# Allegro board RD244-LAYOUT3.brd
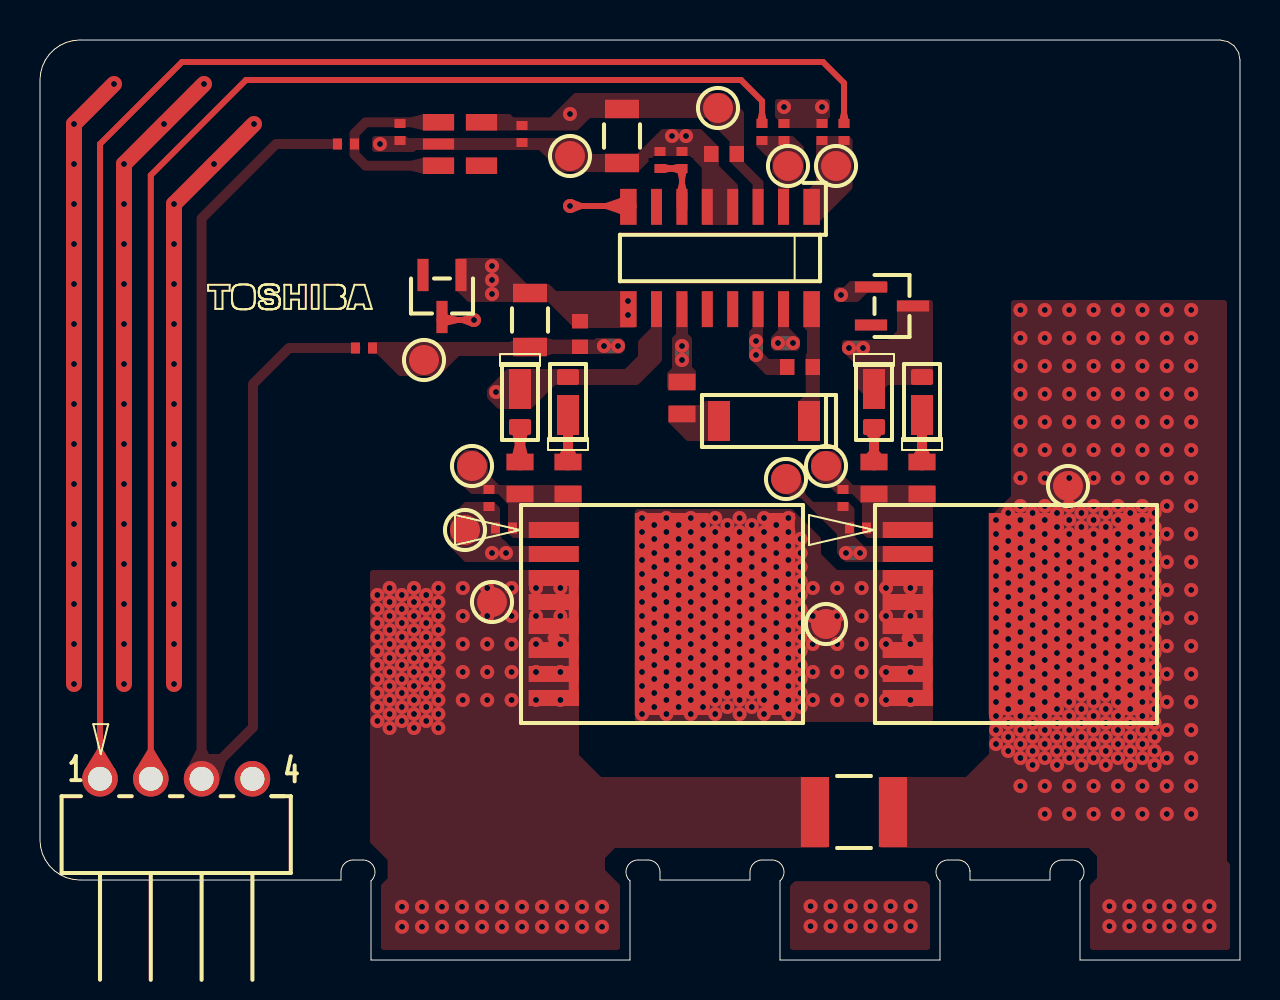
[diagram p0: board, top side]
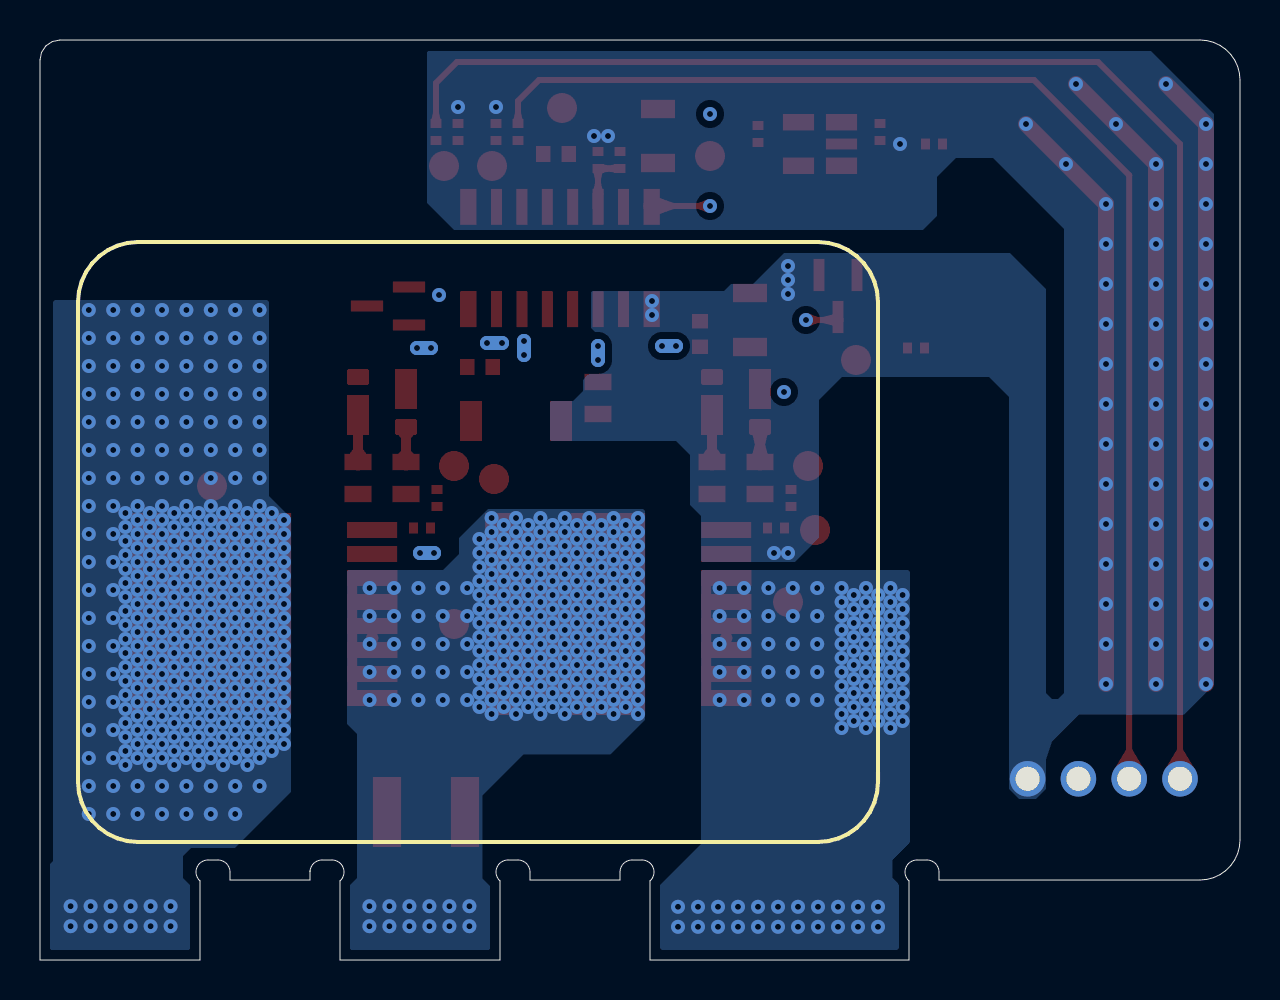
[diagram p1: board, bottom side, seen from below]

Outline 60 x 46 mm; copper layers: TOP, CONDUCTIVE2, CONDUCTIVE3, CONDUCTIVE4, CONDUCTIVE5, BOTTOM. Coordinates in mm from the lower left corner of the outline.
Outline path: 0,44 0.03,44.35 0.12,44.68 0.27,45 0.47,45.29 0.71,45.53 1,45.73 1.32,45.88 1.65,45.97 2,46 59,46 59.39,45.92 59.71,45.71 59.93,45.37 60,45 60,0 52,0 52,3.95 arc(52.16,4.61) 51.6,5 51.1,5 arc(50.68,4.82) 50.5,4.4 50.5,4 46.5,4 46.5,4.45 46.5,4.45 arc(46.31,4.84) 45.9,5 45.4,5 arc(44.84,4.61) 45,3.95 45,0 37,0 37,3.95 arc(37.16,4.61) 36.6,5 36.1,5 arc(35.68,4.82) 35.5,4.4 35.5,4 31,4 31,4.4 arc(30.82,4.82) 30.4,5 29.9,5 arc(29.34,4.61) 29.5,3.95 29.5,0 16.55,0 16.55,3.95 arc(16.71,4.61) 16.15,5 15.65,5 arc(15.23,4.82) 15.05,4.4 15.05,4 2,4 1.65,4.03 1.32,4.12 1,4.27 0.71,4.47 0.47,4.71 0.27,5 0.12,5.32 0.03,5.65 0,6 0,44

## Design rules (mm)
constraint set DEFAULT: 

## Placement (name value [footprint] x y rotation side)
C701  -  [FTP_65]  39.1 41.4 270 top
C702  -  [FTP_65]  37.2 41.4 270 top
C703  -  [FTP_65]  32.1 40 270 top
C704  -  [FTP_15]  29.1 41.2 90 top
C705  -  [KC01670AKP]  34.2 40.3 0 top
C706  -  [KC01670AKP]  38 29.65 0 top
C707  -  [FTP_15]  24.5 32 270 top
C708  -  [KC01670AKP]  27 31.3 270 top
C709  -  [FTP_65]  40.9 21.6 0 top
C710  -  [FTP_65]  23.2 21.6 0 top
C711  -  [DC835R1AKP]  40.7 7.4 0 top
C712  -  [FTP_65]  18 41.4 90 top
C713  -  [FTP_65]  24.1 41.3 90 top
CN702  -  [LOCAL_TSW_104_08_G_S_RA_A]  3 9.06 0 top
D701  -  [FTP_81]  36.2 26.95 0 top
D702  -  [US2H_A]  44.1 27.9 90 top
D703  -  [FTP_27]  42.6 32.7 270 top
D704  -  [US2H_A]  41.7 27.9 270 top
D705  -  [US2H_A]  26.4 27.9 90 top
D706  -  [FTP_27]  20.1 33.2 180 top
D707  -  [US2H_A]  24 27.9 270 top
DP701  -  [DTP815]  39.8 39.7 0 top
DP702  -  [DTP815]  37.4 39.7 0 top
DP703  -  [DTP815]  33.9 42.6 270 top
DP704  -  [DTP815]  26.5 40.2 0 top
DP705  -  [DTP815]  39.3 24.7 0 top
DP706  -  [DTP815]  21.6 24.7 0 top
DP707  -  [DTP815]  51.4 23.7 0 top
DP708  -  [DTP815]  39.3 16.8 0 top
DP709  -  [DTP815]  22.6 17.9 0 top
DP710  -  [DTP815]  19.2 30 0 top
DP711  -  [DTP815]  37.3 24.05 0 top
DP712  -  [DTP815]  21.25 21.5 0 top
IC701  -  [I8K123]  34 35.1 180 top
IC702  -  [DI8G1K]  21 40.8 270 top
NOREF  -  []  7.2 31.35 0 top
NOREF#2  -  []  34.05 35.15 0 top
NOREF#3  -  []  38.1 20.9 180 bottom
Q701  -  [LOCAL_TOLL_A]  48.7 17.3 270 top
Q702  -  [LOCAL_TOLL_A]  31 17.3 270 top
R701  -  [KC00050AKP]  40.2 41.4 270 top
R702  -  [KC00050AKP]  36.1 41.4 270 top
R703  -  [KC00050AKP]  16.2 30.6 180 top
R704  -  [DR810K]  32.1 28.1 90 top
R705  -  [DR810K]  44.1 24.1 270 top
R706  -  [DR810K]  41.7 24.1 270 top
R707  -  [KC00050AKP]  40.15 23.1 90 top
R708  -  [DR810K]  26.4 24.1 270 top
R709  -  [DR810K]  24 24.1 270 top
R710  -  [KC00050AKP]  22.45 23.1 90 top
R711  -  [KC00050AKP]  31 40 270 top
R712  -  [KC00050AKP]  15.3 40.8 0 top

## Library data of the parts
C701-C703 C709 C710 C712 C713 = PRT_52: alternate symbols: (T:FTP_65;B:FTP_66)
C704 C707 = PRT_46: alternate symbols: (T:FTP_15;B:FTP_16)
C705 C706 C708 = C1608: alternate symbols: (T:KC01670AKP;B:KC01670BKP)
C711 = K03S007Y: alternate symbols: (T:DC835R1AKP;B:DC835R1BKP)
CN702 = TSW-104-08-G-S-RA: alternate symbols: (T:Local_TSW_104_08_G_S_RA_A;B:Local_TSW_104_08_G_S_RA_B)
D701 = PRT_14: alternate symbols: (T:FTP_81;B:FTP_82)
D702 D704 D705 D707 = CUHS15S30: alternate symbols: (T:US2H_A;B:US2H_B)
D703 D706 = PRT_25: alternate symbols: (T:FTP_27;B:FTP_31)
DP701-DP712 = DTP815: alternate symbols: (T:DTP815;B:DTP915)
IC701 = UCC21330: alternate symbols: (T:I8K123;B:I9K123)
IC702 = TCR1HF50B: alternate symbols: (T:DI8G1K;B:DI9G1K)
Q701 Q702 = NchMOSFET_TOLL-01: alternate symbols: (T:Local_TOLL_A;B:Local_TOLL_B)
R701-R703 R707 R710-R712 = GDM010004481: alternate symbols: (T:KC00050AKP;B:KC00050BKP)
R704-R706 R708 R709 = R2012: alternate symbols: (T:DR810K;B:DR910K)

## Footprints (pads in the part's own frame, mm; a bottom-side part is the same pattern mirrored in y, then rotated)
DC835R1AKP
  rect 1.41x3.5 smd: 1(-1.95,0) 2(1.95,0)
DI8G1K
  rect 0.825x1.56 smd: 1(-1.087,-1.075) 3(1.087,-1.075) 4(1.087,1.075) 5(-1.087,1.075)
  rect 0.55x1.56 smd: 2(0,-1.075)
DR810K
  rect 0.83x1.35 smd: 1(-0.8,0) 2(0.8,0)
DTP815
  round 1.5 smd: 1(0,0)
FTP_15
  rect 0.92x1.7 smd: 1(-1.35,0) 2(1.35,0)
FTP_27
  rect 0.55x1.61 smd: A(-0.95,-1.05) C(0,1.05) NC(0.95,-1.05)
FTP_65
  rect 0.45x0.55 smd: 1(-0.425,0) 2(0.425,0)
FTP_81
  rect 1.1x2 smd: A(-2.25,0) C(2.25,0)
I8K123
  rect 0.825x1.795 smd: 1(-4.583,-2.558) 8(4.583,-2.558) 9(4.583,2.558) 16(-4.583,2.558)
  rect 0.55x1.795 smd: 2(-3.175,-2.558) 3(-1.905,-2.558) 4(-0.635,-2.558) 5(0.635,-2.558) 6(1.905,-2.558) 7(3.175,-2.558) 10(3.175,2.558) 11(1.905,2.558) 12(0.635,2.558) 13(-0.635,2.558) 14(-1.905,2.558) 15(-3.175,2.558)
KC00050AKP
  rect 0.45x0.55 smd: 1(-0.425,0) 2(0.425,0)
KC01670AKP
  rect 0.72x0.8 smd: 1(-0.64,0) 2(0.64,0)
LOCAL_TOLL_A
  custom 0.625x0.625 smd: (1.2,-5.31)
  rect 0.8x2.5 smd: 1(-4.2,-5.31) 2(-3,-5.31) 3(-1.8,-5.31) 4(-0.6,-5.31) 5(0.6,-5.31) 6(1.8,-5.31) 7(3,-5.31) 8(4.2,-5.31)
  custom 2x2 smd: 9(0,2.74)
LOCAL_TSW_104_08_G_S_RA_A
  round 1.778 hole 1.2: 1(0,0) 2(2.54,0) 3(5.08,0) 4(7.62,0)
US2H_A
  custom 0.2x0.2 smd: A(1.25,0)
  rect 2x1.1 smd: C(-0.65,0)

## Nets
VCC5R0_1: C704.2 C705.2 C713.2 DP703.1 IC701.3 IC701.8 IC702.5
VCC18R0_1: CN702.3 R703.2 R712.1
OUTH: C701.2 CN702.1 DP701.1 IC701.1 R701.1 R701.2
OUTL: C702.2 CN702.2 DP702.1 IC701.2 R702.1 R702.2
PN: C701.1 C702.1 C703.1 C704.1 C705.1 C707.1 C708.1 C710.1 C712.1 C713.1 CN702.4 D706.A DP704.1 DP712.1 IC701.4 IC701.5 IC701.9 IC702.2 Q702.2 R710.1 R711.1
SIG0013: C706.1 C706.2 C709.1 C709.2 D701.C D702.C D703.A D704.A DP705.1 DP711.1 IC701.14 IC701.16 Q701.1 Q701.2 R705.1 R705.2 R706.1 R706.2 R707.1 R707.2
SIG0017: C710.2 D705.C D707.A DP706.1 Q702.1 R708.1 R708.2 R709.1 R709.2 R710.2
SIG00112: D702.A D703.C D704.C IC701.15
SIG00114: D705.A D706.C D707.C IC701.10
SIG00115: C711.1 C711.2 DP707.1 DP709.1 Q701.9 Q702.3 Q702.4 Q702.5 Q702.6 Q702.7 Q702.8
SIG00117: DP708.1 Q701.3 Q701.4 Q701.5 Q701.6 Q701.7 Q701.8 Q702.9
SIG00121: C707.2 C708.2 D701.A DP710.1 IC701.11 R703.1 R704.1 R704.2
SIG00122: C703.2 IC701.6 R711.2
SIG00127: C712.2 IC702.1 IC702.3 R712.2

Pads without a net: D703 NC; D706 NC; IC701 7 12 13; IC702 4

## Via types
v1: diameter 0.7, hole 0.3, TOP to BOTTOM, 791 vias

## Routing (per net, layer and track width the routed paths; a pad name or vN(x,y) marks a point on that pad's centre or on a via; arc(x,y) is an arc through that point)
VCC5R0_1: length 7.5
  TOP w0.3: v1(26.5,37.7) 29.14,37.7
  TOP w0.825: 29.14,37.7 29.42,37.7
  CONDUCTIVE3 w0.3: v1(26.5,42.3) v1(26.5,37.7)
OUTH: length 73.1
  TOP w0.3: CN702.1 3,40.8 7.1,44.9 39.15,44.9 40.2,43.85 40.2,42
  TOP w0.45: R701.1 40.2,42
OUTL: length 64.3
  TOP w0.3: CN702.2 5.54,39.24 10.3,44 35.05,44 36.1,42.95 36.1,42
  TOP w0.45: 36.1,42 R702.1
PN: length 92.1
  TOP w0.8: v1(10.7,41.8) v1(8.7,39.8) v1(6.7,37.8) v1(6.7,35.8) v1(6.7,33.8) v1(6.7,31.8) v1(6.7,29.8) v1(6.7,27.8) v1(6.7,25.8) v1(6.7,23.8) v1(6.7,21.8) v1(6.7,19.8) v1(6.7,17.8) v1(6.7,15.8) v1(6.7,13.8) ; v1(1.7,13.8) v1(1.7,15.8) v1(1.7,17.8) v1(1.7,19.8) v1(1.7,21.8) v1(1.7,23.8) v1(1.7,25.8) v1(1.7,27.8) v1(1.7,29.8) v1(1.7,31.8) v1(1.7,33.8) v1(1.7,35.8) v1(1.7,37.8) v1(1.7,39.8) v1(1.7,41.8) v1(3.7,43.8) ; v1(8.2,43.8) v1(6.2,41.8) v1(4.2,39.8) v1(4.2,37.8) v1(4.2,35.8) v1(4.2,33.8) v1(4.2,31.8) v1(4.2,29.8) v1(4.2,27.8) v1(4.2,25.8) v1(4.2,23.8) v1(4.2,21.8) v1(4.2,19.8) v1(4.2,17.8) v1(4.2,15.8) v1(4.2,13.8)
  vias: v1(17,40.8) v1(22.6,34.7) v1(22.6,34) v1(22.6,33.3) v1(22.6,20.35) v1(23.3,20.35) v1(29.4,32.95) v1(29.4,32.25) v1(31.6,41.2) v1(32.3,41.2) v1(37.2,42.65) v1(39.1,42.65)
SIG0013: length 5.5
  TOP w0.5: 44.1,26.73 44.1,25.19 ; 41.7,26.41 41.7,25.11
  TOP w0.8: D704.A 41.7,26.41
  TOP w0.83: 44.1,25.19 R705.1 ; 41.7,25.11 R706.1
  TOP w1.1: D702.C 44.1,26.73
  BOTTOM w0.7: v1(40.3,20.35) v1(41,20.35) ; v1(35.8,30.95) v1(35.8,30.25)
  vias: v1(40.05,33.25)
SIG0017: length 4.1
  TOP w0.5: 24,25.11 24,26.41 ; 26.4,25.21 26.4,26.76
  TOP w0.8: 24,26.41 D707.A
  TOP w0.83: R709.1 24,25.11 ; R708.1 26.4,25.21
  TOP w1.1: 26.4,26.76 D705.C
SIG00112: length 1.4
  BOTTOM w0.7: v1(40.45,30.6) v1(41.15,30.6) ; v1(37.65,30.85) v1(36.9,30.85)
SIG00114: length 5.7
  TOP w0.3: v1(21.7,32) 20.31,32
  TOP w0.55: 20.31,32 20.1,32
  CONDUCTIVE3 w0.3: v1(21.7,32) 21.7,29.5 v1(22.8,28.4)
SIG00115:
  vias: v1(16.87,18.25) v1(16.87,17.55) v1(16.87,16.85) v1(16.87,16.15) v1(16.87,15.45) v1(16.87,14.75) v1(16.87,14.05) v1(16.87,13.35) v1(16.87,12.65) v1(16.87,11.95) v1(17.48,18.6) v1(17.48,17.9) v1(17.48,17.2) v1(17.48,16.5) v1(17.48,15.8) v1(17.48,15.1) v1(17.48,14.4) v1(17.48,13.7) v1(17.48,13) v1(17.48,12.3) v1(17.48,11.6) v1(18.09,18.25) v1(18.09,17.55) v1(18.09,16.85) v1(18.09,16.15) v1(18.09,15.45) v1(18.09,14.75) v1(18.09,14.05) v1(18.09,13.35) v1(18.09,12.65) v1(18.09,11.95) v1(18.1,2.66) v1(18.1,1.66) v1(18.7,18.6) v1(18.7,17.9) v1(18.7,17.2) v1(18.7,16.5) v1(18.7,15.8) v1(18.7,15.1) v1(18.7,14.4) v1(18.7,13.7) v1(18.7,13) v1(18.7,12.3) v1(18.7,11.6) v1(19.1,2.66) v1(19.1,1.66) v1(19.31,18.25) v1(19.31,17.55) v1(19.31,16.85) v1(19.31,16.15) v1(19.31,15.45) v1(19.31,14.75) v1(19.31,14.05) v1(19.31,13.35) v1(19.31,12.65) v1(19.31,11.95) v1(19.92,18.6) v1(19.92,17.9) v1(19.92,17.2) v1(19.92,16.5) v1(19.92,15.8) v1(19.92,15.1) v1(19.92,14.4) v1(19.92,13.7) v1(19.92,13) v1(19.92,12.3) v1(19.92,11.6) v1(20.1,2.66) v1(20.1,1.66) v1(21.14,18.6) v1(21.14,17.2) v1(21.14,15.8) v1(21.14,14.4) v1(21.14,13) v1(21.1,2.66) v1(21.1,1.66) v1(22.1,2.66) v1(22.1,1.66) v1(22.36,18.6) v1(22.36,17.2) v1(22.36,15.8) v1(22.36,14.4) v1(22.36,13) v1(23.1,2.66) v1(23.1,1.66) v1(23.58,18.6) v1(23.58,17.2) v1(23.58,15.8) v1(23.58,14.4) v1(23.58,13) v1(24.1,2.66) v1(24.1,1.66) v1(24.8,18.6) v1(24.8,17.2) v1(24.8,15.8) v1(24.8,14.4) v1(24.8,13) v1(25.1,2.66) v1(25.1,1.66) v1(26.02,18.6) v1(26.02,17.2) v1(26.02,15.8) v1(26.02,14.4) v1(26.02,13) v1(26.1,2.66) v1(26.1,1.66) v1(27.1,2.66) v1(27.1,1.66) v1(28.1,2.66) v1(28.1,1.66) v1(47.8,22) v1(47.8,21.3) v1(47.8,20.6) v1(47.8,19.9) v1(47.8,19.2) v1(47.8,18.5) v1(47.8,17.8) v1(47.8,17.1) v1(47.8,16.4) v1(47.8,15.7) v1(47.8,15) v1(47.8,14.3) v1(47.8,13.6) v1(47.8,12.9) v1(47.8,12.2) v1(47.8,11.5) v1(47.8,10.8) v1(48.41,22.35) v1(48.41,21.65) v1(48.41,20.95) v1(48.41,20.25) v1(48.41,19.55) v1(48.41,18.85) v1(48.41,18.15) v1(48.41,17.45) v1(48.41,16.75) v1(48.41,16.05) v1(48.41,15.35) v1(48.41,14.65) v1(48.41,13.95) v1(48.41,13.25) v1(48.41,12.55) v1(48.41,11.85) v1(48.41,11.15) v1(48.41,10.45) v1(49.02,32.5) v1(49.02,31.1) v1(49.02,29.7) v1(49.02,28.3) v1(49.02,26.9) v1(49.02,25.5) v1(49.02,24.1) v1(49.02,22.7) v1(49.02,22) v1(49.02,21.3) v1(49.02,20.6) v1(49.02,19.9) v1(49.02,19.2) v1(49.02,18.5) v1(49.02,17.8) v1(49.02,17.1) v1(49.02,16.4) v1(49.02,15.7) v1(49.02,15) v1(49.02,14.3) v1(49.02,13.6) v1(49.02,12.9) v1(49.02,12.2) v1(49.02,11.5) v1(49.02,10.8) v1(49.02,10.1) v1(49.02,8.7) v1(49.63,22.35) v1(49.63,21.65) v1(49.63,20.95) v1(49.63,20.25) v1(49.63,19.55) v1(49.63,18.85) v1(49.63,18.15) v1(49.63,17.45) v1(49.63,16.75) v1(49.63,16.05) v1(49.63,15.35) v1(49.63,14.65) v1(49.63,13.95) v1(49.63,13.25) v1(49.63,12.55) v1(49.63,11.85) v1(49.63,11.15) v1(49.63,10.45) v1(49.63,9.75) v1(50.24,32.5) v1(50.24,31.1) v1(50.24,29.7) v1(50.24,28.3) v1(50.24,26.9) v1(50.24,25.5) v1(50.24,24.1) v1(50.24,22.7) v1(50.24,22) v1(50.24,21.3) v1(50.24,20.6) v1(50.24,19.9) v1(50.24,19.2) v1(50.24,18.5) v1(50.24,17.8) v1(50.24,17.1) v1(50.24,16.4) v1(50.24,15.7) v1(50.24,15) v1(50.24,14.3) v1(50.24,13.6) v1(50.24,12.9) v1(50.24,12.2) v1(50.24,11.5) v1(50.24,10.8) v1(50.24,10.1) v1(50.24,8.7) v1(50.24,7.3) v1(50.85,22.35) v1(50.85,21.65) v1(50.85,20.95) v1(50.85,20.25) v1(50.85,19.55) v1(50.85,18.85) v1(50.85,18.15) v1(50.85,17.45) v1(50.85,16.75) v1(50.85,16.05) v1(50.85,15.35) v1(50.85,14.65) v1(50.85,13.95) v1(50.85,13.25) v1(50.85,12.55) v1(50.85,11.85) v1(50.85,11.15) v1(50.85,10.45) v1(50.85,9.75) v1(51.46,32.5) v1(51.46,31.1) v1(51.46,29.7) v1(51.46,28.3) v1(51.46,26.9) v1(51.46,25.5) v1(51.46,24.1) v1(51.46,22.7) v1(51.46,22) v1(51.46,21.3) v1(51.46,20.6) v1(51.46,19.9) v1(51.46,19.2) v1(51.46,18.5) v1(51.46,17.8) v1(51.46,17.1) v1(51.46,16.4) v1(51.46,15.7) v1(51.46,15) v1(51.46,14.3) v1(51.46,13.6) v1(51.46,12.9) v1(51.46,12.2) v1(51.46,11.5) v1(51.46,10.8) v1(51.46,10.1) v1(51.46,8.7) v1(51.46,7.3) v1(52.07,22.35) v1(52.07,21.65) v1(52.07,20.95) v1(52.07,20.25) v1(52.07,19.55) v1(52.07,18.85) v1(52.07,18.15) v1(52.07,17.45) v1(52.07,16.75) v1(52.07,16.05) v1(52.07,15.35) v1(52.07,14.65) v1(52.07,13.95) v1(52.07,13.25) v1(52.07,12.55) v1(52.07,11.85) v1(52.07,11.15) v1(52.07,10.45) v1(52.07,9.75) v1(52.68,32.5) v1(52.68,31.1) v1(52.68,29.7) v1(52.68,28.3) v1(52.68,26.9) v1(52.68,25.5) v1(52.68,24.1) v1(52.68,22.7) v1(52.68,22) v1(52.68,21.3) v1(52.68,20.6) v1(52.68,19.9) v1(52.68,19.2) v1(52.68,18.5) v1(52.68,17.8) v1(52.68,17.1) v1(52.68,16.4) v1(52.68,15.7) v1(52.68,15) v1(52.68,14.3) v1(52.68,13.6) v1(52.68,12.9) v1(52.68,12.2) v1(52.68,11.5) v1(52.68,10.8) v1(52.68,10.1) v1(52.68,8.7) v1(52.68,7.3) v1(53.29,22.35) v1(53.29,21.65) v1(53.29,20.95) v1(53.29,20.25) v1(53.29,19.55) v1(53.29,18.85) v1(53.29,18.15) v1(53.29,17.45) v1(53.29,16.75) v1(53.29,16.05) v1(53.29,15.35) v1(53.29,14.65) v1(53.29,13.95) v1(53.29,13.25) v1(53.29,12.55) v1(53.29,11.85) v1(53.29,11.15) v1(53.29,10.45) v1(53.29,9.75) v1(53.47,2.69) v1(53.47,1.69) v1(53.9,32.5) v1(53.9,31.1) v1(53.9,29.7) v1(53.9,28.3) v1(53.9,26.9) v1(53.9,25.5) v1(53.9,24.1) v1(53.9,22.7) v1(53.9,22) v1(53.9,21.3) v1(53.9,20.6) v1(53.9,19.9) v1(53.9,19.2) v1(53.9,18.5) v1(53.9,17.8) v1(53.9,17.1) v1(53.9,16.4) v1(53.9,15.7) v1(53.9,15) v1(53.9,14.3) v1(53.9,13.6) v1(53.9,12.9) v1(53.9,12.2) v1(53.9,11.5) v1(53.9,10.8) v1(53.9,10.1) v1(53.9,8.7) v1(53.9,7.3) v1(54.51,22.35) v1(54.51,21.65) v1(54.51,20.95) v1(54.51,20.25) v1(54.51,19.55) v1(54.51,18.85) v1(54.51,18.15) v1(54.51,17.45) v1(54.51,16.75) v1(54.51,16.05) v1(54.51,15.35) v1(54.51,14.65) v1(54.51,13.95) v1(54.51,13.25) v1(54.51,12.55) v1(54.51,11.85) v1(54.51,11.15) v1(54.51,10.45) v1(54.51,9.75) v1(54.47,2.69) v1(54.47,1.69) v1(55.12,32.5) v1(55.12,31.1) v1(55.12,29.7) v1(55.12,28.3) v1(55.12,26.9) v1(55.12,25.5) v1(55.12,24.1) v1(55.12,22.7) v1(55.12,22) v1(55.12,21.3) v1(55.12,20.6) v1(55.12,19.9) v1(55.12,19.2) v1(55.12,18.5) v1(55.12,17.8) v1(55.12,17.1) v1(55.12,16.4) v1(55.12,15.7) v1(55.12,15) v1(55.12,14.3) v1(55.12,13.6) v1(55.12,12.9) v1(55.12,12.2) v1(55.12,11.5) v1(55.12,10.8) v1(55.12,10.1) v1(55.12,8.7) v1(55.12,7.3) v1(55.47,2.69) v1(55.47,1.69) v1(55.73,22.35) v1(55.73,21.65) v1(55.73,20.95) v1(55.73,20.25) v1(55.73,19.55) v1(55.73,18.85) v1(55.73,18.15) v1(55.73,17.45) v1(55.73,16.75) v1(55.73,16.05) v1(55.73,15.35) v1(55.73,14.65) v1(55.73,13.95) v1(55.73,13.25) v1(55.73,12.55) v1(55.73,11.85) v1(55.73,11.15) v1(55.73,10.45) v1(55.73,9.75) v1(56.34,32.5) v1(56.34,31.1) v1(56.34,29.7) v1(56.34,28.3) v1(56.34,26.9) v1(56.34,25.5) v1(56.34,24.1) v1(56.34,22.7) v1(56.34,21.3) v1(56.34,19.9) v1(56.34,18.5) v1(56.34,17.1) v1(56.34,15.7) v1(56.34,14.3) v1(56.34,12.9) v1(56.34,11.5) v1(56.34,10.1) v1(56.34,8.7) v1(56.34,7.3) v1(56.47,2.69) v1(56.47,1.69) v1(57.47,2.69) v1(57.47,1.69) v1(57.56,32.5) v1(57.56,31.1) v1(57.56,29.7) v1(57.56,28.3) v1(57.56,26.9) v1(57.56,25.5) v1(57.56,24.1) v1(57.56,22.7) v1(57.56,21.3) v1(57.56,19.9) v1(57.56,18.5) v1(57.56,17.1) v1(57.56,15.7) v1(57.56,14.3) v1(57.56,12.9) v1(57.56,11.5) v1(57.56,10.1) v1(57.56,8.7) v1(57.56,7.3) v1(58.47,2.69) v1(58.47,1.69)
SIG00117:
  vias: v1(30.1,22.1) v1(30.1,21.4) v1(30.1,20.7) v1(30.1,20) v1(30.1,19.3) v1(30.1,18.6) v1(30.1,17.9) v1(30.1,17.2) v1(30.1,16.5) v1(30.1,15.8) v1(30.1,15.1) v1(30.1,14.4) v1(30.1,13.7) v1(30.1,13) v1(30.1,12.3) v1(30.71,21.75) v1(30.71,21.05) v1(30.71,20.35) v1(30.71,19.65) v1(30.71,18.95) v1(30.71,18.25) v1(30.71,17.55) v1(30.71,16.85) v1(30.71,16.15) v1(30.71,15.45) v1(30.71,14.75) v1(30.71,14.05) v1(30.71,13.35) v1(30.71,12.65) v1(31.32,22.1) v1(31.32,21.4) v1(31.32,20.7) v1(31.32,20) v1(31.32,19.3) v1(31.32,18.6) v1(31.32,17.9) v1(31.32,17.2) v1(31.32,16.5) v1(31.32,15.8) v1(31.32,15.1) v1(31.32,14.4) v1(31.32,13.7) v1(31.32,13) v1(31.32,12.3) v1(31.93,21.75) v1(31.93,21.05) v1(31.93,20.35) v1(31.93,19.65) v1(31.93,18.95) v1(31.93,18.25) v1(31.93,17.55) v1(31.93,16.85) v1(31.93,16.15) v1(31.93,15.45) v1(31.93,14.75) v1(31.93,14.05) v1(31.93,13.35) v1(31.93,12.65) v1(32.54,22.1) v1(32.54,21.4) v1(32.54,20.7) v1(32.54,20) v1(32.54,19.3) v1(32.54,18.6) v1(32.54,17.9) v1(32.54,17.2) v1(32.54,16.5) v1(32.54,15.8) v1(32.54,15.1) v1(32.54,14.4) v1(32.54,13.7) v1(32.54,13) v1(32.54,12.3) v1(33.15,21.75) v1(33.15,21.05) v1(33.15,20.35) v1(33.15,19.65) v1(33.15,18.95) v1(33.15,18.25) v1(33.15,17.55) v1(33.15,16.85) v1(33.15,16.15) v1(33.15,15.45) v1(33.15,14.75) v1(33.15,14.05) v1(33.15,13.35) v1(33.15,12.65) v1(33.76,22.1) v1(33.76,21.4) v1(33.76,20.7) v1(33.76,20) v1(33.76,19.3) v1(33.76,18.6) v1(33.76,17.9) v1(33.76,17.2) v1(33.76,16.5) v1(33.76,15.8) v1(33.76,15.1) v1(33.76,14.4) v1(33.76,13.7) v1(33.76,13) v1(33.76,12.3) v1(34.37,21.75) v1(34.37,21.05) v1(34.37,20.35) v1(34.37,19.65) v1(34.37,18.95) v1(34.37,18.25) v1(34.37,17.55) v1(34.37,16.85) v1(34.37,16.15) v1(34.37,15.45) v1(34.37,14.75) v1(34.37,14.05) v1(34.37,13.35) v1(34.37,12.65) v1(34.98,22.1) v1(34.98,21.4) v1(34.98,20.7) v1(34.98,20) v1(34.98,19.3) v1(34.98,18.6) v1(34.98,17.9) v1(34.98,17.2) v1(34.98,16.5) v1(34.98,15.8) v1(34.98,15.1) v1(34.98,14.4) v1(34.98,13.7) v1(34.98,13) v1(34.98,12.3) v1(35.59,21.75) v1(35.59,21.05) v1(35.59,20.35) v1(35.59,19.65) v1(35.59,18.95) v1(35.59,18.25) v1(35.59,17.55) v1(35.59,16.85) v1(35.59,16.15) v1(35.59,15.45) v1(35.59,14.75) v1(35.59,14.05) v1(35.59,13.35) v1(35.59,12.65) v1(36.2,22.1) v1(36.2,21.4) v1(36.2,20.7) v1(36.2,20) v1(36.2,19.3) v1(36.2,18.6) v1(36.2,17.9) v1(36.2,17.2) v1(36.2,16.5) v1(36.2,15.8) v1(36.2,15.1) v1(36.2,14.4) v1(36.2,13.7) v1(36.2,13) v1(36.2,12.3) v1(36.81,21.75) v1(36.81,21.05) v1(36.81,20.35) v1(36.81,19.65) v1(36.81,18.95) v1(36.81,18.25) v1(36.81,17.55) v1(36.81,16.85) v1(36.81,16.15) v1(36.81,15.45) v1(36.81,14.75) v1(36.81,14.05) v1(36.81,13.35) v1(36.81,12.65) v1(37.42,22.1) v1(37.42,21.4) v1(37.42,20.7) v1(37.42,20) v1(37.42,19.3) v1(37.42,18.6) v1(37.42,17.9) v1(37.42,17.2) v1(37.42,16.5) v1(37.42,15.8) v1(37.42,15.1) v1(37.42,14.4) v1(37.42,13.7) v1(37.42,13) v1(37.42,12.3) v1(38.03,21.05) v1(38.03,20.35) v1(38.03,19.65) v1(38.03,18.95) v1(38.03,18.25) v1(38.03,17.55) v1(38.03,16.85) v1(38.03,16.15) v1(38.03,15.45) v1(38.03,14.75) v1(38.03,14.05) v1(38.03,13.35) v1(38.03,12.65) v1(38.53,2.69) v1(38.53,1.69) v1(38.64,18.6) v1(38.64,17.2) v1(38.64,15.8) v1(38.64,14.4) v1(38.64,13) v1(39.53,2.69) v1(39.53,1.69) v1(39.86,18.6) v1(39.86,17.2) v1(39.86,15.8) v1(39.86,14.4) v1(39.86,13) v1(40.53,2.69) v1(40.53,1.69) v1(41.08,18.6) v1(41.08,17.2) v1(41.08,15.8) v1(41.08,14.4) v1(41.08,13) v1(41.53,2.69) v1(41.53,1.69) v1(42.3,18.6) v1(42.3,17.2) v1(42.3,15.8) v1(42.3,14.4) v1(42.3,13) v1(42.53,2.69) v1(42.53,1.69) v1(43.52,18.6) v1(43.52,17.2) v1(43.52,15.8) v1(43.52,14.4) v1(43.52,13) v1(43.53,2.69) v1(43.53,1.69)
SIG00121: length 1.4
  BOTTOM w0.7: v1(28.2,30.7) v1(28.9,30.7) ; v1(32.1,30.7) v1(32.1,30)
SIG00122: length 3.1
  TOP w0.3: 32.1,39.4 32.1,38.3 ; 31.18,39.58 31.92,39.58
  TOP w0.45: 31.92,39.58 C703.2 32.1,39.4 ; R711.2 31.18,39.58
  TOP w0.54: 32.1,38.3 32.1,37.6

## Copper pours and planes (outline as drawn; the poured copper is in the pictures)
VCC5R0_1 on TOP: 35.63,38.77 34.52,39.88 34.49,39.92 34.48,39.98 34.48,40.92 33.3,42.1 27.5,42.1 26.92,41.52 26.87,41.49 26.81,41.48 22.07,41.48 21.66,41.89 22.07,42.3 23.44,42.3 23.5,42.29 23.54,42.26 23.66,42.14 25.52,42.14 26.69,43.31 26.73,43.34 26.79,43.35 34.19,43.35 34.25,43.34 34.29,43.31 35.16,42.44 35.19,42.4 35.2,42.34 35.2,39.9 36.14,38.96 36.17,38.92 36.18,38.86 36.18,37.46 35.91,37.18 35.63,37.46
VCC18R0_1 on TOP: 8.52,9.14 8.46,9.18 8.43,9.24 8.28,9.53 7.96,9.43 7.92,9.42 7.88,9.42 7.83,9.42 7.73,9.24 7.45,9.1 7.26,9.35 7.27,9.4 7.29,9.46 7.83,10.54 7.83,37.08 7.85,37.18 7.9,37.26 11.62,40.98 11.7,41.03 11.8,41.05 14.88,41.05 15.12,40.8 14.88,40.55 11.9,40.55 8.33,36.98 8.33,10.54 8.45,10.3 8.97,10.3 10.4,11.73 10.4,28.8 10.42,28.9 10.47,28.98 12.27,30.78 12.35,30.83 12.45,30.85 15.78,30.85 16.02,30.6 15.78,30.35 12.55,30.35 10.9,28.7 10.9,11.63 10.88,11.53 10.83,11.45 9.3,9.93 8.92,8.78 8.61,8.62 8.45,8.94
OUTL on TOP: 37.05,37.3 36.94,37.34 36.9,37.45 36.9,39.05 36.64,39.31 36.61,39.35 36.6,39.41 36.6,39.9 35.84,40.66 35.81,40.7 35.8,40.76 35.8,41.05 35.84,41.16 35.95,41.2 37.59,41.2 37.65,41.19 37.69,41.16 38.16,40.69 38.19,40.65 38.2,40.59 38.2,39.36 38.19,39.3 38.16,39.26 37.45,38.55 37.45,37.45 37.41,37.34 37.3,37.3
PN on TOP: 26.76,31.6 26.7,31.61 26.66,31.64 25.4,32.9 21.46,32.9 21.4,32.91 21.36,32.94 20.84,33.46 20.81,33.5 20.8,33.56 20.8,34.95 20.84,35.06 20.95,35.1 22.99,35.1 23.05,35.09 23.09,35.06 24.35,33.8 25.39,33.8 25.45,33.79 25.49,33.76 25.8,33.45 29.65,33.45 29.76,33.41 29.8,33.3 29.8,31.75 29.76,31.64 29.65,31.6
PN on TOP: 33.24,36.75 33.13,36.79 33.09,36.9 33.09,39.61 32.5,40.2 30.7,40.2 29.94,39.44 29.9,39.41 29.84,39.4 26.11,39.4 26.05,39.41 26.01,39.44 24.95,40.5 18.8,40.5 18.74,40.44 18.7,40.41 18.64,40.4 16.75,40.4 16.64,40.44 16.6,40.55 16.6,41.04 16.61,41.1 16.64,41.14 16.66,41.16 16.7,41.19 16.76,41.2 18.24,41.2 18.3,41.19 18.34,41.16 18.4,41.1 26.79,41.1 26.85,41.09 26.89,41.06 27.65,40.3 29.85,40.3 31.06,41.51 31.1,41.54 31.16,41.55 32.99,41.55 33.05,41.54 33.09,41.51 33.91,40.69 33.94,40.65 33.95,40.59 33.95,39.7 34.86,38.79 34.89,38.75 34.9,38.69 34.9,36.9 34.86,36.79 34.75,36.75
PN on BOTTOM, CONDUCTIVE2, CONDUCTIVE5: outline of 112 points within 1.3,8.05 40.65,45.45 ; 5 cut-outs
SIG0013 on TOP: 41.41,21.1 41.35,21.11 41.31,21.14 41.14,21.31 41.11,21.35 41.1,21.41 41.1,22.8 40.6,23.3 39.91,23.3 39.85,23.31 39.81,23.34 39.3,23.85 39.11,23.85 39.05,23.86 39.01,23.89 38.59,24.31 38.56,24.35 38.55,24.41 38.55,24.99 38.56,25.04 38.59,25.09 38.91,25.41 38.95,25.44 39.01,25.45 39.64,25.45 39.7,25.44 39.74,25.41 40.06,25.09 40.09,25.05 40.1,24.99 40.1,24.75 40.1,24.74 40.1,24.3 40.65,23.75 44.65,23.75 44.76,23.71 44.8,23.6 44.8,22.91 44.79,22.85 44.76,22.81 44.65,22.7 44.65,21.25 44.61,21.14 44.5,21.1
SIG0013 on TOP: 36.36,29.25 36.3,29.26 36.26,29.29 35.49,30.06 35.46,30.1 35.45,30.16 35.45,31.36 35.46,31.41 35.63,31.6 35.63,31.7 35.63,31.72 35.63,32.54 35.83,32.81 36.14,32.68 36.16,32.61 36.15,32.54 36.15,30.35 36.45,30.05 37.55,30.05 37.66,30.01 37.7,29.9 37.7,29.4 37.66,29.29 37.55,29.25
SIG0013 on TOP: 40.34,19.9 40.28,19.91 40.23,19.94 39.89,20.28 39.86,20.33 39.85,20.39 39.85,21.29 38.07,23.07 37.11,23.33 37.07,23.34 37.04,23.36 37.02,23.39 37.01,23.54 37.14,23.62 37.18,23.62 37.6,23.5 37.85,23.75 37.73,24.17 37.74,24.26 37.8,24.33 37.84,24.35 37.88,24.36 37.97,24.32 38.02,24.24 38.28,23.28 38.66,22.91 40.06,22.91 40.1,22.9 40.34,22.9 40.4,22.89 40.44,22.86 40.68,22.62 40.71,22.57 40.73,22.51 40.73,21.18 41.2,20.7 43.24,20.7 43.35,20.66 43.39,20.55 43.39,20.05 43.35,19.94 43.24,19.9
SIG0013 on CONDUCTIVE2, CONDUCTIVE5: 44.8,22.89 44.79,22.85 44.77,22.82 44.65,22.7 44.65,20 44.62,19.93 44.55,19.9 40.29,19.9 40.25,19.91 40.22,19.93 39.95,20.2 39.93,20.23 39.92,20.27 39.92,22.62 37.93,24.62 37.91,24.65 37.9,24.69 37.9,28.5 37.15,29.25 36.19,29.25 36.15,29.26 36.12,29.28 35.48,29.92 35.46,29.95 35.45,29.99 35.45,33.35 35.48,33.42 35.55,33.45 39.5,33.45 39.97,33.92 40,33.94 40.04,33.95 44.7,33.95 44.77,33.92 44.8,33.85 ; 2 cut-outs
SIG0017 on TOP: 23.71,21.1 23.65,21.11 23.61,21.14 23.44,21.31 23.41,21.35 23.4,21.41 23.4,22.8 22.9,23.3 21.61,23.3 21.55,23.31 21.51,23.34 20.89,23.96 20.86,24 20.85,24.06 20.85,25.04 20.86,25.1 20.89,25.14 21.21,25.46 21.25,25.49 21.31,25.5 21.79,25.5 21.85,25.49 21.89,25.46 22.36,24.99 22.39,24.95 22.4,24.89 22.4,24.3 22.95,23.75 26.95,23.75 27.06,23.71 27.1,23.6 27.1,22.91 27.09,22.85 27.06,22.81 26.95,22.7 26.95,21.25 26.91,21.14 26.8,21.1
SIG00112 on TOP: 41.21,28.3 41.15,28.31 41.11,28.34 40.84,28.61 40.81,28.65 40.8,28.71 40.8,29.75 40.14,30.41 40.11,30.45 40.1,30.51 40.1,30.85 40.14,30.96 40.25,31 42.4,31 42.85,31.45 42.85,32.85 42.89,32.96 43,33 44.5,33 44.61,32.96 44.65,32.85 44.65,28.9 44.61,28.79 44.5,28.75 42.4,28.75 41.99,28.34 41.95,28.31 41.89,28.3
SIG00112 on CONDUCTIVE3: 36.65,30 36.58,30.03 36.55,30.1 36.55,31.45 36.58,31.52 36.65,31.55 41.4,31.55 41.47,31.52 41.5,31.45 41.5,30.1 41.47,30.03 41.4,30
SIG00114 on TOP: 23,27.55 22.91,27.57 22.83,27.62 22.42,28.03 22.37,28.11 22.35,28.2 22.35,28.45 22.37,28.54 22.42,28.62 23.28,29.48 23.36,29.53 23.45,29.55 29.25,29.55 29.9,30.2 29.9,30.85 29.92,30.94 29.97,31.02 30.55,31.6 30.55,32.65 30.62,32.83 30.8,32.9 30.85,32.9 31.03,32.83 31.1,32.65 31.1,30.05 31.08,29.96 31.03,29.88 29.97,28.82 29.89,28.77 29.8,28.75 25.75,28.75 24.62,27.62 24.54,27.57 24.45,27.55
SIG00115 on TOP: 52.65,0.5 52.54,0.54 52.5,0.65 52.5,3.69 52.51,3.75 52.54,3.79 52.85,4.1 52.85,5.14 52.86,5.18 52.44,5.6 42.1,5.6 41.99,5.64 41.95,5.75 41.95,9 41.99,9.11 42.1,9.15 46.3,9.15 47.41,10.26 47.43,10.27 47.45,10.29 47.45,22.04 47.46,22.1 47.49,22.14 48.55,23.2 48.55,32.85 48.59,32.96 48.7,33 59.2,33 59.31,32.96 59.35,32.85 59.35,4.95 59.46,4.84 59.49,4.8 59.5,4.74 59.5,0.65 59.46,0.54 59.35,0.5
SIG00115 on TOP: 17.2,0.5 17.09,0.54 17.05,0.65 17.05,3.69 17.06,3.75 17.09,3.79 17.38,4.08 17.38,5 16.54,5.84 16.51,5.88 16.5,5.94 16.5,19.35 16.54,19.46 16.65,19.5 26.8,19.5 26.91,19.46 26.95,19.35 26.95,10.25 28.05,9.15 39.3,9.15 39.41,9.11 39.45,9 39.45,5.75 39.41,5.64 39.3,5.6 28.75,5.6 28.25,5.1 28.25,4.5 28.58,4.17 28.96,3.79 28.99,3.75 29,3.69 29,0.65 28.96,0.54 28.85,0.5
SIG00115 on BOTTOM: 17.2,0.5 17.09,0.54 17.05,0.65 17.05,3.69 17.06,3.74 17.08,3.78 17.1,3.82 17.12,3.85 17.38,4.11 17.38,5 16.54,5.84 16.51,5.88 16.5,5.94 16.5,19.35 16.54,19.46 16.65,19.5 26.8,19.5 26.91,19.46 26.95,19.35 26.95,5.8 28.57,4.18 28.58,4.17 28.96,3.79 28.99,3.75 29,3.69 29,0.65 28.96,0.54 28.85,0.5
SIG00115 on BOTTOM, CONDUCTIVE5: 52.6,0.5 52.53,0.53 52.5,0.6 52.5,3.71 52.51,3.75 52.53,3.78 52.85,4.1 52.85,5.15 52.86,5.18 52.44,5.6 50.31,5.6 50.25,5.61 50.21,5.64 47.49,8.36 47.46,8.4 47.45,8.46 47.45,22.04 47.46,22.1 47.49,22.14 48.55,23.2 48.55,32.85 48.59,32.96 48.7,33 59.2,33 59.31,32.96 59.35,32.85 59.35,4.95 59.47,4.83 59.49,4.8 59.5,4.76 59.5,0.6 59.47,0.53 59.4,0.5
SIG00115 on CONDUCTIVE2, CONDUCTIVE3: 17.15,0.5 17.08,0.53 17.05,0.6 17.05,3.71 17.06,3.75 17.08,3.78 17.38,4.08 17.38,5 16.54,5.84 16.51,5.88 16.5,5.94 16.5,19.35 16.54,19.46 16.65,19.5 26.8,19.5 26.91,19.46 26.95,19.35 26.95,5.8 28.57,4.18 28.97,3.78 28.99,3.75 29,3.71 29,0.6 28.97,0.53 28.9,0.5
SIG00115 on CONDUCTIVE2, CONDUCTIVE4: 52.6,0.5 52.53,0.53 52.5,0.6 52.5,3.71 52.51,3.75 52.53,3.78 52.85,4.1 52.85,5.15 52.86,5.18 52.44,5.6 50.31,5.6 50.25,5.61 50.21,5.64 47.49,8.36 47.46,8.4 47.45,8.46 47.45,22.04 47.46,22.1 47.49,22.14 48.55,23.2 48.55,32.85 48.59,32.96 48.7,33 59.2,33 59.31,32.96 59.35,32.85 59.35,4.95 59.47,4.83 59.49,4.8 59.5,4.76 59.5,0.6 59.47,0.53 59.4,0.5
SIG00115 on CONDUCTIVE3: 52.6,0.5 52.53,0.53 52.5,0.6 52.5,3.71 52.51,3.75 52.53,3.78 52.85,4.1 52.85,5.15 52.86,5.18 52.44,5.6 50.31,5.6 50.25,5.61 50.21,5.64 47.49,8.36 47.46,8.4 47.45,8.46 47.45,22.04 47.46,22.1 47.49,22.14 48.55,23.2 48.55,32.85 48.59,32.96 48.7,33 59.2,33 59.31,32.96 59.35,32.85 59.35,4.95 59.47,4.83 59.49,4.8 59.5,4.76 59.5,0.6 59.47,0.53 59.4,0.5
SIG00115 on CONDUCTIVE4, CONDUCTIVE5: 17.15,0.5 17.08,0.53 17.05,0.6 17.05,3.71 17.06,3.75 17.08,3.78 17.1,3.82 17.12,3.85 17.38,4.11 17.38,5 16.54,5.84 16.51,5.88 16.5,5.94 16.5,19.35 16.54,19.46 16.65,19.5 26.8,19.5 26.91,19.46 26.95,19.35 26.95,5.8 28.57,4.18 28.58,4.17 28.97,3.78 28.99,3.75 29,3.71 29,0.6 28.97,0.53 28.9,0.5
SIG00117 on TOP: 29.9,11.9 29.79,11.94 29.75,12.05 29.75,22.4 29.79,22.51 29.9,22.55 37.54,22.55 37.6,22.54 37.64,22.51 39.01,21.14 39.04,21.1 39.05,21.04 39.05,20.3 39.85,19.5 44.5,19.5 44.61,19.46 44.65,19.35 44.65,12.05 44.61,11.94 44.5,11.9
SIG00117 on TOP: 37.65,0.5 37.54,0.54 37.5,0.65 37.5,3.64 37.51,3.7 37.54,3.74 37.7,3.9 37.75,3.93 37.81,3.94 44.24,3.94 44.3,3.93 44.35,3.9 44.46,3.79 44.49,3.75 44.5,3.69 44.5,0.65 44.46,0.54 44.35,0.5
SIG00117 on BOTTOM, CONDUCTIVE2, CONDUCTIVE3, CONDUCTIVE4, CONDUCTIVE5: 37.6,0.5 37.53,0.53 37.5,0.6 37.5,3.66 37.51,3.7 37.53,3.73 37.88,4.08 37.88,8.22 35.83,10.28 31.52,10.28 31.48,10.28 31.45,10.3 29.79,11.96 29.76,12 29.75,12.06 29.75,22.4 29.79,22.51 29.9,22.55 37.56,22.55 37.6,22.54 37.63,22.52 39.02,21.13 39.04,21.1 39.05,21.06 39.05,20.3 39.85,19.5 44.55,19.5 44.62,19.47 44.65,19.4 44.65,11.84 44.64,11.8 44.62,11.77 44.15,11.3 44.15,4.1 44.47,3.78 44.49,3.75 44.5,3.71 44.5,0.6 44.47,0.53 44.4,0.5
SIG00121 on TOP: 31.5,28.5 31.39,28.54 31.35,28.65 31.35,29.29 31.36,29.35 31.39,29.39 31.6,29.6 31.6,31.04 31.61,31.1 31.64,31.14 31.8,31.3 31.8,33.15 31.84,33.26 31.95,33.3 32.25,33.3 32.36,33.26 32.4,33.15 32.4,31.3 32.56,31.14 32.59,31.1 32.6,31.04 32.6,29.65 32.76,29.49 32.79,29.45 32.8,29.39 32.8,28.65 32.76,28.54 32.65,28.5
SIG00121 on TOP: 18.01,29.2 17.95,29.21 17.91,29.24 16.85,30.3 16.55,30.3 16.44,30.34 16.4,30.45 16.4,30.75 16.44,30.86 16.55,30.9 23.47,30.9 23.69,30.99 23.75,31.06 23.8,31.09 23.86,31.1 24.36,31.1 24.4,31.11 24.45,31.11 25.23,31.11 25.28,31.11 25.33,31.1 25.56,31.05 25.59,31.04 25.62,31.02 27.72,31.02 27.76,31.06 27.8,31.09 27.86,31.1 28.99,31.1 29.05,31.09 29.09,31.06 29.21,30.94 29.24,30.9 29.25,30.84 29.25,30.56 29.24,30.5 29.21,30.46 29.09,30.34 29.05,30.31 28.99,30.3 25.62,30.3 25.59,30.28 25.56,30.27 25.36,30.23 25.27,30.2 25.19,30.19 23.81,30.19 23.77,30.19 23.72,30.2 20.95,30.2 19.99,29.24 19.95,29.21 19.89,29.2
SIG00121 on CONDUCTIVE3: 27.95,29.55 27.88,29.58 27.85,29.65 27.85,31 27.88,31.07 27.95,31.1 32.4,31.1 32.47,31.07 32.5,31 32.5,29.65 32.47,29.58 32.4,29.55
SIG00127 on TOP: 19.2,39.3 18.56,39.46 16.29,39.46 16.19,39.48 16.11,39.54 15.55,40.1 15.49,40.18 15.47,40.27 15.47,41.33 15.49,41.42 15.55,41.5 16.11,42.06 16.19,42.12 16.29,42.14 18.56,42.14 19.2,42.3 19.25,42.3 19.93,42.3 20.34,41.89 19.93,41.48 19.25,41.48 19.2,41.48 18.56,41.64 16.39,41.64 15.97,41.22 15.97,40.38 16.39,39.96 18.56,39.96 19.2,40.12 19.25,40.12 19.93,40.12 20.34,39.71 19.93,39.3 19.25,39.3

Small or netless copper shapes (teardrops, artwork), in the pictures only: 21 on TOP, 4 on CONDUCTIVE3

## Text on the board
Ref Des/Silkscreen Top: 1 | 4
PAGE_OUTLINE: 1 | 4
SYMBOL-2-TOP: SAA009602010 | SGB009602000 | DP712 | R710 | CN702 | C710 | R712 | R703 | DP709 | DP706 | DP710 | R709 | D706 | IC702 | DP704 | DP705 | R707 | Q702 | C706 | DP711 | D701 | C711 | DP708 | C705 | Q701 | DP702 | DP701 | PN | CN701 | VSW | PFCOUT | C712 | D707 | C713 | C707 | C708 | C704 | D705 | R708 | R704 | R711 | C703 | C709 | IC701 | D703 | DP703 | D704 | R706 | R702 | D702 | R705 | DP707 | C702 | C701 | R701 | RD244 FBUnit1 | 1 | 4
SYMBOL-2-BOTTOM: Heatsink
